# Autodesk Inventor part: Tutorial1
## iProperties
Created: 2009-05
Part Number: Tutorial1
Document SubType Name: Modeling
Designer: Sham
Density: 1 g/cm^3
Author: Sham
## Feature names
1. Extrusion1
